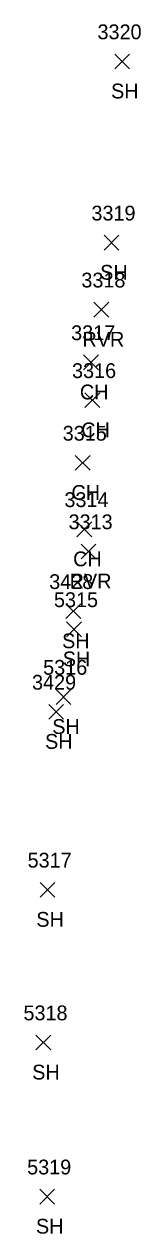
# Model space of a CAD drawing. Extents: x 1601151 to 1602912, y 499508 to 501770.
# Drawn here: x 1601150.9 to 1601166.6, y 500621.4 to 500784.8 of the extents above; entities that cross this region are included whole.
import ezdxf

# ---------------------------------------------------------------- set-up
doc = ezdxf.new("R2010")
doc.units = 0
for name, color, linetype in [('L_A', 7, 'Continuous'), ('L_I', 7, 'Continuous'), ('L_TIC', 7, 'Continuous')]:
    doc.layers.add(name, color=color, linetype=linetype)

msp = doc.modelspace()

# ---------------------------------------------------------------- linework, layer by layer
at = {"layer": 'L_TIC'}
for points in [[(1601163.13, 500778.8), (1601165.13, 500780.8)], [(1601165.13, 500778.8), (1601163.13, 500780.8)], [(1601161.67, 500754.3), (1601163.67, 500756.3)], [(1601163.67, 500754.3), (1601161.67, 500756.3)], [(1601160.3, 500745.25), (1601162.3, 500747.25)], [(1601162.3, 500745.25), (1601160.3, 500747.25)], [(1601158.92, 500738.13), (1601160.92, 500740.13)], [(1601160.92, 500738.13), (1601158.92, 500740.13)], [(1601159.1, 500733.01), (1601161.1, 500735.01)], [(1601161.1, 500733.01), (1601159.1, 500735.01)], [(1601157.78, 500724.55), (1601159.78, 500726.55)], [(1601159.78, 500724.55), (1601157.78, 500726.55)], [(1601158.01, 500715.57), (1601160.01, 500717.57)], [(1601160.01, 500715.57), (1601158.01, 500717.57)], [(1601158.57, 500712.58), (1601160.57, 500714.58)], [(1601160.57, 500712.58), (1601158.57, 500714.58)], [(1601156.53, 500704.5), (1601158.53, 500706.5)], [(1601158.53, 500704.5), (1601156.53, 500706.5)], [(1601156.61, 500702.05), (1601158.61, 500704.05)], [(1601158.61, 500702.05), (1601156.61, 500704.05)], [(1601155.19, 500692.91), (1601157.19, 500694.91)], [(1601157.19, 500692.91), (1601155.19, 500694.91)], [(1601154.22, 500690.9), (1601156.22, 500692.9)], [(1601156.22, 500690.9), (1601154.22, 500692.9)], [(1601153.04, 500666.85), (1601155.04, 500668.85)], [(1601155.04, 500666.85), (1601153.04, 500668.85)], [(1601152.48, 500646.21), (1601154.48, 500648.21)], [(1601154.48, 500646.21), (1601152.48, 500648.21)], [(1601152.99, 500625.38), (1601154.99, 500627.38)], [(1601154.99, 500625.38), (1601152.99, 500627.38)]]:
    msp.add_lwpolyline(points, dxfattribs=at)

# ---------------------------------------------------------------- texts
at = {"layer": 'L_A'}
for s, p in [('SH', (1601162.62, 500774.8)), ('SH', (1601161.15, 500750.3)), ('RVR', (1601158.76, 500741.25)), ('CH', (1601158.41, 500734.13)), ('CH', (1601158.59, 500729.01)), ('CH', (1601157.27, 500720.55)), ('CH', (1601157.5, 500711.57)), ('RVR', (1601157.03, 500708.58)), ('SH', (1601156.01, 500700.5)), ('SH', (1601156.1, 500698.05)), ('SH', (1601154.68, 500688.91)), ('SH', (1601153.71, 500686.9)), ('SH', (1601152.53, 500662.85)), ('SH', (1601151.97, 500642.21)), ('SH', (1601152.48, 500621.38))]:
    msp.add_text(s, height=2, dxfattribs=at).set_placement(p)
at = {"layer": 'L_I'}
for s, p in [('3320', (1601160.79, 500782.8)), ('3319', (1601159.97, 500758.3)), ('3318', (1601158.61, 500749.25)), ('3317', (1601157.23, 500742.13)), ('3316', (1601157.35, 500737.01)), ('3315', (1601156.09, 500728.55)), ('3314', (1601156.32, 500719.57)), ('3313', (1601156.88, 500716.58)), ('3428', (1601154.27, 500708.5)), ('5315', (1601154.91, 500706.05)), ('5316', (1601153.45, 500696.91)), ('3429', (1601151.95, 500694.9)), ('5317', (1601151.35, 500670.85)), ('5318', (1601150.79, 500650.21)), ('5319', (1601151.29, 500629.38))]:
    msp.add_text(s, height=2, dxfattribs=at).set_placement(p)

doc.saveas('drawing.dxf')
